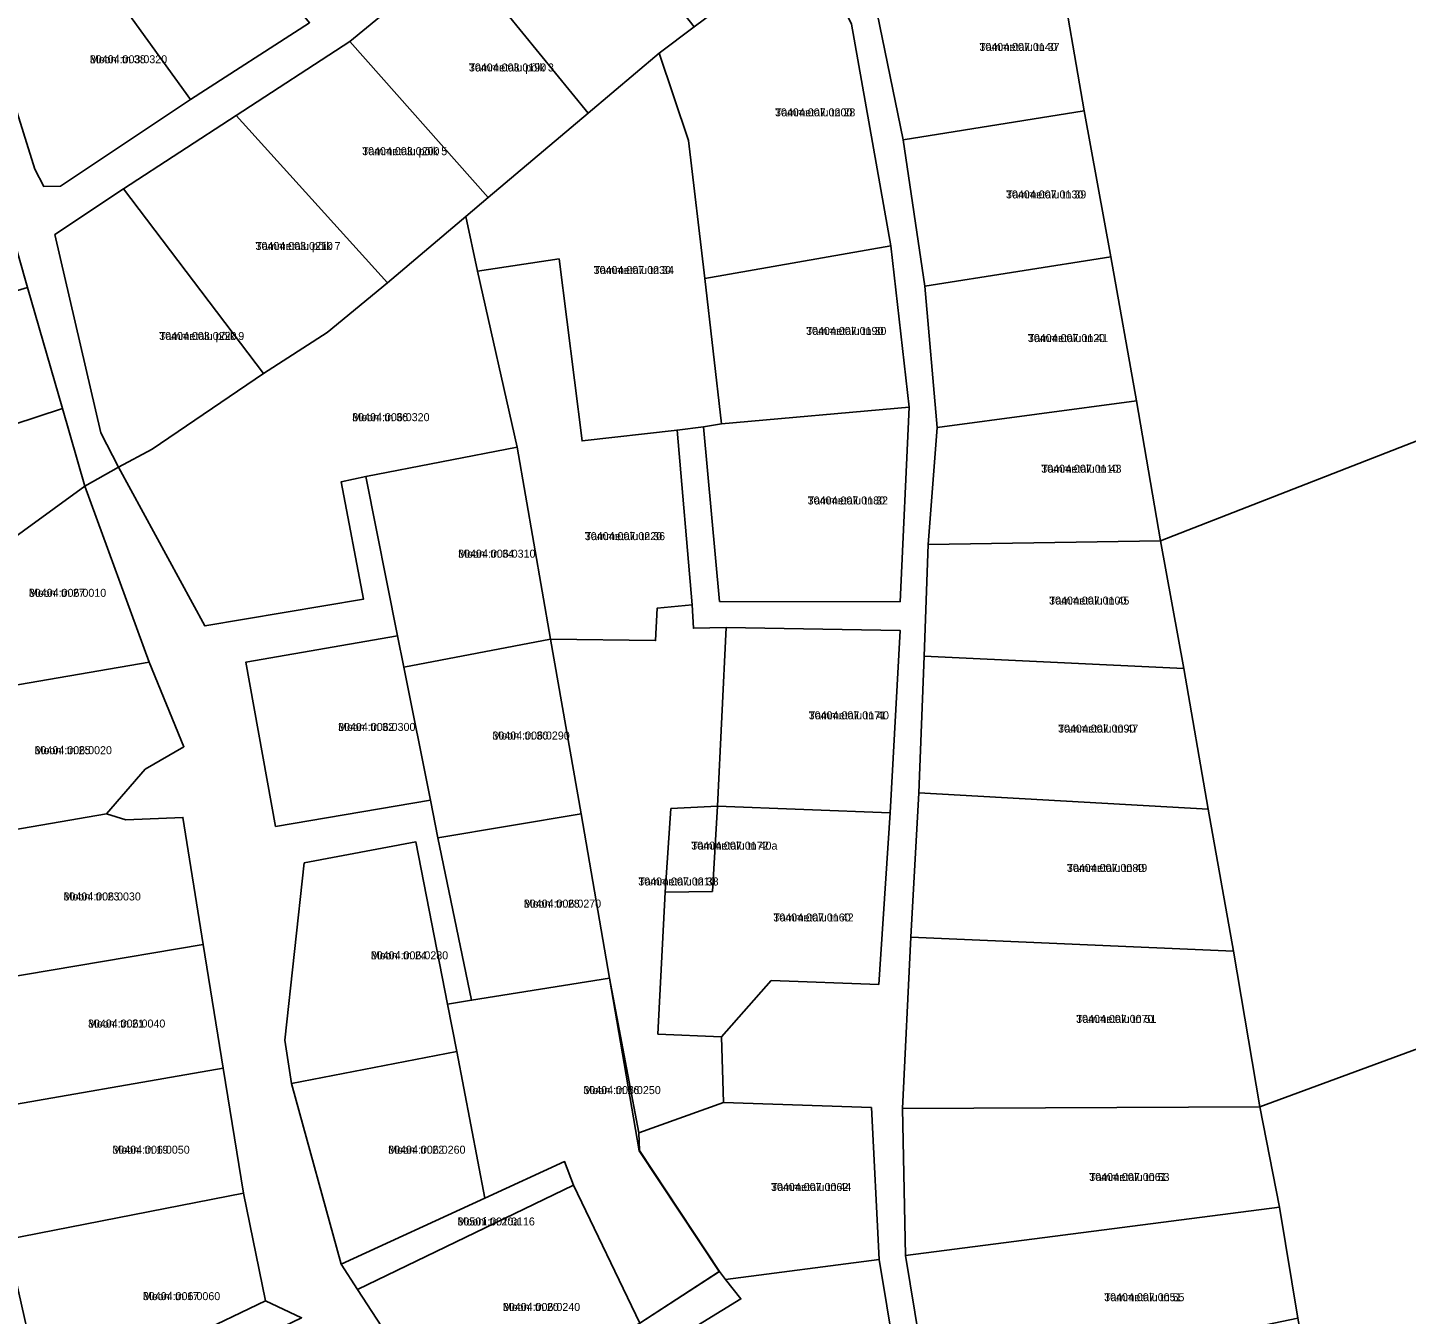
# Model space of a CAD drawing. Extents: x 542681 to 554572, y 6566489 to 6580482.
# Drawn here: x 544263.2 to 544521.7, y 6577011.6 to 6577252.9 of the extents above; entities that cross this region are included whole.
import ezdxf

# ---------------------------------------------------------------- set-up
doc = ezdxf.new("R2010")
doc.units = 0
for name, color, linetype in [('L_AADRESS', 7, 'Continuous'), ('PIIR', 7, 'Continuous'), ('TUNNUS', 7, 'Continuous')]:
    doc.layers.add(name, color=color, linetype=linetype)

msp = doc.modelspace()

# ---------------------------------------------------------------- linework, layer by layer
at = {"layer": 'PIIR'}
for points in [[(544456.52, 6577265.21), (544452.65, 6577285.75), (545218.92, 6577608.77), (545224.16, 6577610.98), (545231.09, 6577528.66), (545236.55, 6577455.03), (545231.68, 6577453.11), (544923.07, 6577331.26), (544475.6, 6577156.69), (544471.1, 6577182.9), (544466.29, 6577209.93), (544461.31, 6577237.31)], [(544475.6, 6577156.69), (544923.07, 6577331.26), (545231.68, 6577453.11), (545236.55, 6577455.03), (545247.19, 6577343.96), (545247.53, 6577327.48), (545244.51, 6577326.53), (545190.34, 6577306.46), (544821.86, 6577171.21), (544494.23, 6577050.54), (544489.31, 6577079.73), (544484.54, 6577106.35), (544480, 6577132.74)], [(544508.33, 6576971.98), (544504.11, 6576995.85), (544501.39, 6577010.89), (544497.94, 6577031.69), (544494.23, 6577050.54), (544821.86, 6577171.21), (545190.34, 6577306.46), (545193.01, 6577298.86), (545134.4, 6577265.31), (545034.06, 6577204.02), (544998.25, 6577194.68), (544965.83, 6577161.37), (544819.08, 6577074.48), (544704.29, 6576998.99), (544688.78, 6576996.97)], [(544364.05, 6577283.62), (544388.19, 6577253.04), (544381.63, 6577248.14), (544368.3, 6577236.86), (544343.79, 6577266.92)], [(544274.81, 6577265.67), (544284.39, 6577272.38), (544286, 6577273.11), (544294.22, 6577280.25), (544316.1, 6577253.81), (544293.74, 6577239.41)], [(544417.71, 6577253.54), (544425.07, 6577211.96), (544390.19, 6577205.83), (544387.14, 6577231.76), (544381.63, 6577248.14), (544388.19, 6577253.04), (544408.54, 6577268.25), (544410.06, 6577269.38)], [(544343.79, 6577266.92), (544368.3, 6577236.86), (544349.57, 6577221.02), (544323.61, 6577250.29)], [(544266.26, 6577223.12), (544264.6, 6577226.38), (544256.03, 6577253.6), (544274.81, 6577265.67), (544293.74, 6577239.41), (544269.36, 6577223.2)], [(544461.31, 6577237.31), (544427.37, 6577231.84), (544421.97, 6577258.14), (544456.52, 6577265.21)], [(544323.61, 6577250.29), (544349.57, 6577221.02), (544345.39, 6577217.48), (544330.7, 6577205.05), (544302.31, 6577236.4)], [(544387.14, 6577231.76), (544390.19, 6577205.83), (544393.29, 6577178.58), (544389.97, 6577178.01), (544384.98, 6577177.43), (544367.17, 6577175.4), (544362.86, 6577209.53), (544347.54, 6577207.22), (544345.39, 6577217.48), (544349.57, 6577221.02), (544368.3, 6577236.86), (544381.63, 6577248.14)], [(544302.31, 6577236.4), (544330.7, 6577205.05), (544319.38, 6577195.7), (544307.46, 6577188.02), (544281.19, 6577222.69)], [(544466.29, 6577209.93), (544431.45, 6577204.42), (544427.37, 6577231.84), (544461.31, 6577237.31)], [(544276.94, 6577176.9), (544268.33, 6577214.08), (544281.19, 6577222.69), (544307.46, 6577188.02), (544286.55, 6577173.88), (544280.28, 6577170.48)], [(544280.28, 6577170.48), (544286.55, 6577173.88), (544307.46, 6577188.02), (544319.38, 6577195.7), (544330.7, 6577205.05), (544345.39, 6577217.48), (544347.54, 6577207.22), (544354.99, 6577174.24), (544326.62, 6577168.71), (544322.03, 6577167.75), (544326.22, 6577145.74), (544296.46, 6577140.71)], [(544428.49, 6577181.73), (544393.29, 6577178.58), (544390.19, 6577205.83), (544425.07, 6577211.96)], [(544367.17, 6577175.4), (544384.98, 6577177.43), (544387.83, 6577144.66), (544381.25, 6577144.03), (544380.96, 6577137.96), (544361.26, 6577138.19), (544354.99, 6577174.24), (544347.54, 6577207.22), (544362.86, 6577209.53)], [(544471.1, 6577182.9), (544433.76, 6577177.93), (544431.45, 6577204.42), (544466.29, 6577209.93)], [(544223, 6577192.18), (544263.2, 6577204.14), (544269.75, 6577181.48), (544228.43, 6577167.92)], [(544234.67, 6577140.84), (544228.43, 6577167.92), (544269.75, 6577181.48), (544273.95, 6577166.88), (544238.7, 6577141.31)], [(544426.79, 6577145.23), (544392.96, 6577145.3), (544389.97, 6577178.01), (544393.29, 6577178.58), (544428.49, 6577181.73)], [(544475.6, 6577156.69), (544432.08, 6577155.97), (544433.76, 6577177.93), (544471.1, 6577182.9)], [(544326.62, 6577168.71), (544354.99, 6577174.24), (544361.26, 6577138.19), (544333.73, 6577132.98), (544332.56, 6577138.86)], [(544238.7, 6577141.31), (544273.95, 6577166.88), (544286.02, 6577133.9), (544236.96, 6577125.44)], [(544480, 6577132.74), (544431.29, 6577135.04), (544432.08, 6577155.97), (544475.6, 6577156.69)], [(544380.96, 6577137.96), (544381.25, 6577144.03), (544387.83, 6577144.66), (544388.04, 6577140.28), (544394.17, 6577140.39), (544392.54, 6577106.93), (544383.84, 6577106.44), (544382.75, 6577090.75), (544381.39, 6577064.17), (544393.3, 6577063.62), (544393.67, 6577051.35), (544377.8, 6577045.62), (544372.34, 6577074.65), (544366.99, 6577105.49), (544361.26, 6577138.19)], [(544424.96, 6577105.64), (544392.54, 6577106.93), (544394.17, 6577140.39), (544426.79, 6577139.86)], [(544309.71, 6577103.12), (544304.12, 6577133.9), (544332.56, 6577138.86), (544333.73, 6577132.98), (544338.75, 6577108.03)], [(544338.75, 6577108.03), (544333.73, 6577132.98), (544361.26, 6577138.19), (544366.99, 6577105.49), (544340.16, 6577100.96)], [(544484.54, 6577106.35), (544430.31, 6577109.41), (544431.29, 6577135.04), (544480, 6577132.74)], [(544236.96, 6577125.44), (544286.02, 6577133.9), (544292.53, 6577118.03), (544285.26, 6577113.83), (544278.03, 6577105.45), (544242.8, 6577099.39)], [(544489.31, 6577079.73), (544428.8, 6577082.33), (544430.31, 6577109.41), (544484.54, 6577106.35)], [(544422.79, 6577073.49), (544402.63, 6577074.21), (544393.3, 6577063.62), (544381.39, 6577064.17), (544382.75, 6577090.75), (544391.62, 6577090.91), (544392.54, 6577106.93), (544424.96, 6577105.64)], [(544383.84, 6577106.44), (544392.54, 6577106.93), (544391.62, 6577090.91), (544382.75, 6577090.75)], [(544242.8, 6577099.39), (544278.03, 6577105.45), (544281.62, 6577104.36), (544292.35, 6577104.8), (544296.14, 6577080.98), (544248.72, 6577072.99)], [(544340.16, 6577100.96), (544366.99, 6577105.49), (544372.34, 6577074.65), (544346.46, 6577070.51)], [(544311.44, 6577063.05), (544315.09, 6577096.25), (544336.01, 6577100.21), (544341.95, 6577069.79), (544343.71, 6577060.87), (544312.68, 6577054.88)], [(544248.72, 6577072.99), (544296.14, 6577080.98), (544299.89, 6577057.8), (544253.92, 6577049.8)], [(544494.23, 6577050.54), (544427.23, 6577050.19), (544428.8, 6577082.33), (544489.31, 6577079.73)], [(544346.42, 6577070.5), (544372.29, 6577074.64), (544377.9, 6577042.29), (544392.89, 6577019.62), (544378.03, 6577009.97), (544365.54, 6577035.85), (544363.91, 6577040.25), (544348.97, 6577033.42), (544343.71, 6577060.87), (544341.95, 6577069.79)], [(544312.68, 6577054.88), (544343.71, 6577060.87), (544348.97, 6577033.42), (544322.03, 6577021.02)], [(544253.92, 6577049.8), (544299.89, 6577057.8), (544303.68, 6577034.31), (544259.33, 6577025.66)], [(544422.87, 6577021.89), (544394.09, 6577018.12), (544392.94, 6577019.63), (544377.95, 6577042.3), (544377.8, 6577045.62), (544393.67, 6577051.35), (544421.43, 6577050.38)], [(544497.94, 6577031.69), (544427.82, 6577022.67), (544427.23, 6577050.19), (544494.23, 6577050.54)], [(544365.54, 6577035.85), (544325.07, 6577016.28), (544322.03, 6577021.02), (544348.97, 6577033.42), (544363.91, 6577040.25)], [(544259.33, 6577025.66), (544303.68, 6577034.31), (544307.82, 6577014.16), (544266.36, 6576994.23)], [(544343.06, 6576988.63), (544325.07, 6577016.28), (544365.54, 6577035.85), (544378.03, 6577009.97)], [(544501.39, 6577010.89), (544432.12, 6576996.45), (544427.82, 6577022.67), (544497.94, 6577031.69)], [(544411.54, 6576996.24), (544397.14, 6576987.19), (544386.23, 6577007.95), (544396.97, 6577014.51), (544394.09, 6577018.12), (544422.87, 6577021.89), (544427.25, 6576995.48), (544414.19, 6576992.91)]]:
    msp.add_lwpolyline(points, close=True, dxfattribs=at)
for points in [[(544343.79, 6577266.92), (544323.61, 6577250.29), (544302.31, 6577236.4), (544281.19, 6577222.69), (544268.33, 6577214.08), (544276.94, 6577176.9), (544280.28, 6577170.48), (544273.95, 6577166.88), (544269.75, 6577181.48), (544263.2, 6577204.14), (544256.79, 6577226.59), (544250.31, 6577249.52), (544239.96, 6577285.6)], [(544421.97, 6577258.14), (544427.37, 6577231.84), (544431.45, 6577204.42), (544433.76, 6577177.93), (544432.08, 6577155.97), (544431.29, 6577135.04), (544430.31, 6577109.41), (544428.8, 6577082.33), (544427.23, 6577050.19), (544427.82, 6577022.67), (544432.12, 6576996.45)], [(544256.03, 6577253.6), (544264.6, 6577226.38), (544266.26, 6577223.12), (544269.36, 6577223.2), (544293.74, 6577239.41), (544316.1, 6577253.81)], [(544427.25, 6576995.48), (544422.87, 6577021.89), (544421.43, 6577050.38), (544393.67, 6577051.35), (544393.3, 6577063.62), (544402.63, 6577074.21), (544422.79, 6577073.49), (544424.96, 6577105.64), (544426.79, 6577139.86), (544394.17, 6577140.39), (544388.04, 6577140.28), (544387.83, 6577144.66), (544384.98, 6577177.43), (544389.97, 6577178.01), (544392.96, 6577145.3), (544426.79, 6577145.23), (544428.49, 6577181.73), (544425.07, 6577211.96), (544417.71, 6577253.54)], [(544314.6, 6577010.96), (544307.82, 6577014.16), (544303.68, 6577034.31), (544299.89, 6577057.8), (544296.14, 6577080.98), (544292.35, 6577104.8), (544281.62, 6577104.36), (544278.03, 6577105.45), (544285.26, 6577113.83), (544292.53, 6577118.03), (544286.02, 6577133.9), (544273.95, 6577166.88), (544280.28, 6577170.48), (544296.46, 6577140.71), (544326.22, 6577145.74), (544322.03, 6577167.75), (544326.62, 6577168.71), (544332.56, 6577138.86), (544304.12, 6577133.9), (544309.71, 6577103.12), (544338.75, 6577108.03), (544340.16, 6577100.96), (544346.46, 6577070.51), (544341.95, 6577069.79), (544336.01, 6577100.21), (544315.09, 6577096.25), (544311.44, 6577063.05), (544312.68, 6577054.88), (544322.03, 6577021.02), (544325.07, 6577016.28), (544343.06, 6576988.63)], [(544259.33, 6577025.66), (544266.36, 6576994.23), (544307.82, 6577014.16), (544314.6, 6577010.96), (544268.59, 6576988.8), (544283.42, 6576966.41), (544297.5, 6576945.15), (544309.92, 6576926.39), (544323.02, 6576906.59), (544336.6, 6576886.08), (544350.13, 6576865.65), (544363.36, 6576845.67), (544376.61, 6576825.66), (544374.32, 6576824.14), (544359.67, 6576846.22), (544345.3, 6576867.89), (544330.91, 6576889.58), (544316.53, 6576911.27), (544302.13, 6576932.97), (544287.78, 6576954.61), (544264.77, 6576989.29), (544263.5, 6576993.69), (544232.86, 6577132.75)], [(544378.03, 6577009.97), (544392.94, 6577019.63), (544394.09, 6577018.12), (544396.97, 6577014.51), (544386.23, 6577007.95)]]:
    msp.add_lwpolyline(points, dxfattribs=at)

# ---------------------------------------------------------------- texts
at = {"layer": 'L_AADRESS'}
for s, p in [('Tammetalu tn 37', (544441.66, 6577248.53)), ('Mooni tn 38', (544274.89, 6577246.22)), ('Tammetalu põik 3', (544345.95, 6577244.68)), ('Tammetalu tn 28', (544403.35, 6577236.26)), ('Tammetalu põik 5', (544325.94, 6577228.98)), ('Tammetalu tn 39', (544446.65, 6577220.87)), ('Tammetalu põik 7', (544305.95, 6577211.2)), ('Tammetalu tn 34', (544369.34, 6577206.69)), ('Tammetalu tn 30', (544409.17, 6577195.27)), ('Tammetalu põik 9', (544287.89, 6577194.32)), ('Tammetalu tn 41', (544450.75, 6577193.93)), ('Mooni tn 36', (544324.08, 6577179.1)), ('Tammetalu tn 43', (544453.26, 6577169.43)), ('Tammetalu tn 32', (544409.47, 6577163.48)), ('Tammetalu tn 36', (544367.68, 6577156.79)), ('Mooni tn 34', (544343.94, 6577153.5)), ('Mooni tn 27', (544263.46, 6577146.16)), ('Tammetalu tn 45', (544454.73, 6577144.71)), ('Tammetalu tn 40', (544409.66, 6577123.19)), ('Mooni tn 32', (544321.43, 6577121.01)), ('Tammetalu tn 47', (544456.41, 6577120.7)), ('Mooni tn 30', (544350.36, 6577119.4)), ('Mooni tn 25', (544264.53, 6577116.65)), ('Tammetalu tn 40a', (544387.64, 6577098.75)), ('Tammetalu tn 49', (544458.07, 6577094.57)), ('Tammetalu tn 38', (544377.71, 6577092.03)), ('Mooni tn 23', (544269.95, 6577089.22)), ('Mooni tn 28', (544356.25, 6577087.88)), ('Tammetalu tn 42', (544403.03, 6577085.28)), ('Mooni tn 24', (544327.57, 6577078.18)), ('Tammetalu tn 51', (544459.8, 6577066.26)), ('Mooni tn 21', (544274.54, 6577065.39)), ('Mooni tn 26', (544367.42, 6577052.91)), ('Mooni tn 19', (544279.11, 6577041.73)), ('Mooni tn 22', (544330.82, 6577041.73)), ('Tammetalu tn 44', (544402.59, 6577034.74)), ('Tammetalu tn 53', (544462.25, 6577036.61)), ('Mooni tn 20a', (544343.81, 6577028.27)), ('Mooni tn 17', (544284.84, 6577014.27)), ('Tammetalu tn 55', (544465.05, 6577014.07)), ('Mooni tn 20', (544352.32, 6577012.24))]:
    msp.add_text(s, height=1.5, dxfattribs=at).set_placement(p)
at = {"layer": 'TUNNUS'}
for s, p in [('30404:007:0140', (544441.66, 6577248.53)), ('30404:003:0320', (544274.89, 6577246.22)), ('30404:003:0190', (544345.95, 6577244.68)), ('30404:007:0200', (544403.35, 6577236.26)), ('30404:003:0200', (544325.94, 6577228.98)), ('30404:007:0130', (544446.65, 6577220.87)), ('30404:003:0210', (544305.95, 6577211.2)), ('30404:007:0230', (544369.34, 6577206.69)), ('30404:007:0190', (544409.17, 6577195.27)), ('30404:003:0220', (544287.89, 6577194.32)), ('30404:007:0120', (544450.75, 6577193.93)), ('30404:006:0320', (544324.08, 6577179.1)), ('30404:007:0110', (544453.26, 6577169.43)), ('30404:007:0180', (544409.47, 6577163.48)), ('30404:007:0220', (544367.68, 6577156.79)), ('30404:006:0310', (544343.94, 6577153.5)), ('30404:006:0010', (544263.46, 6577146.16)), ('30404:007:0100', (544454.73, 6577144.71)), ('30404:007:0171', (544409.66, 6577123.19)), ('30404:006:0300', (544321.43, 6577121.01)), ('30404:007:0090', (544456.41, 6577120.7)), ('30404:006:0290', (544350.36, 6577119.4)), ('30404:006:0020', (544264.53, 6577116.65)), ('30404:007:0172', (544387.64, 6577098.75)), ('30404:007:0080', (544458.07, 6577094.57)), ('30404:007:0210', (544377.71, 6577092.03)), ('30404:006:0030', (544269.95, 6577089.22)), ('30404:006:0270', (544356.25, 6577087.88)), ('30404:007:0160', (544403.03, 6577085.28)), ('30404:006:0280', (544327.57, 6577078.18)), ('30404:007:0070', (544459.8, 6577066.26)), ('30404:006:0040', (544274.54, 6577065.39)), ('30404:006:0250', (544367.42, 6577052.91)), ('30404:006:0050', (544279.11, 6577041.73)), ('30404:006:0260', (544330.82, 6577041.73)), ('30404:007:0062', (544402.59, 6577034.74)), ('30404:007:0061', (544462.25, 6577036.61)), ('30501:001:0116', (544343.81, 6577028.27)), ('30404:006:0060', (544284.84, 6577014.27)), ('30404:007:0051', (544465.05, 6577014.07)), ('30404:006:0240', (544352.32, 6577012.24))]:
    msp.add_text(s, height=1.5, dxfattribs=at).set_placement(p)

doc.saveas('drawing.dxf')
